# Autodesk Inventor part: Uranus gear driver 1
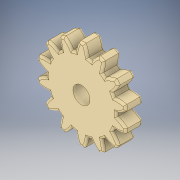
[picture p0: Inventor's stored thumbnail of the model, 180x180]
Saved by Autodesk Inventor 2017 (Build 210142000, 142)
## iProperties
Created: 2016-06
Part Number: Uranus gear driver 1
Material: Generic
Document SubType Name: Modeling
Designer: Stan
Density: 1 g/cm^3
Appearance: Beige
Author: Stan
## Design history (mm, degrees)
sketch "Sketch1"
  geometry: A1 r 11.074 centre (-14.504, 0.302) between (-8.695, 9.73) and (-12.531, 11.198); A2 r 11.074 centre (-14.504, 0.302) between (-8.695, 9.73) and (-12.531, 11.198); A3 r 11.074 centre (2.933, 14.207) between (-8.129, 14.709) and (-7.551, 10.642); A4 r 11.074 centre (2.933, 14.207) between (-8.129, 14.709) and (-7.551, 10.642); A5 r 11.074 centre (-13.198, -6.021) between (-12.056, 4.994) and (-16.149, 4.652); A6 r 11.074 centre (-13.198, -6.021) between (-12.056, 4.994) and (-16.149, 4.652); A7 r 11.074 centre (-3.521, 14.073) between (-13.706, 9.725) and (-11.421, 6.312); A8 r 11.074 centre (-3.521, 14.073) between (-13.706, 9.725) and (-11.421, 6.312); A9 r 11.074 centre (-9.279, -11.152) between (-13.029, -0.732) and (-16.568, -2.815); A10 r 11.074 centre (-9.279, -11.152) between (-13.029, -0.732) and (-16.568, -2.815); A11 r 11.074 centre (-9.279, 11.152) between (-16.568, 2.815) and (-13.029, 0.732); A12 r 11.074 centre (-9.279, 11.152) between (-16.568, 2.815) and (-13.029, 0.732); A13 r 11.074 centre (-3.521, -14.073) between (-11.421, -6.312) and (-13.706, -9.725); A14 r 11.074 centre (-3.521, -14.073) between (-11.421, -6.312) and (-13.706, -9.725); A15 r 11.074 centre (-13.198, 6.021) between (-16.149, -4.652) and (-12.056, -4.994); A16 r 11.074 centre (-13.198, 6.021) between (-16.149, -4.652) and (-12.056, -4.994); A17 r 11.074 centre (2.933, -14.207) between (-7.551, -10.642) and (-8.129, -14.709); A18 r 11.074 centre (2.933, -14.207) between (-7.551, -10.642) and (-8.129, -14.709); A19 r 11.074 centre (-14.504, -0.302) between (-12.531, -11.198) and (-8.695, -9.73); A20 r 11.074 centre (-14.504, -0.302) between (-12.531, -11.198) and (-8.695, -9.73); A21 r 11.074 centre (8.807, -11.528) between (-2.186, -12.865) and (-0.942, -16.779); A22 r 11.074 centre (8.807, -11.528) between (-2.186, -12.865) and (-0.942, -16.779); A23 r 11.074 centre (-12.937, -6.565) between (-6.431, -15.526) and (-3.612, -12.539); A24 r 11.074 centre (-12.937, -6.565) between (-6.431, -15.526) and (-3.612, -12.539); A25 r 11.074 centre (12.937, -6.565) between (3.612, -12.539) and (6.431, -15.526); A26 r 11.074 centre (12.937, -6.565) between (3.612, -12.539) and (6.431, -15.526); A27 r 11.074 centre (-8.807, -11.528) between (0.942, -16.779) and (2.186, -12.865); A28 r 11.074 centre (-8.807, -11.528) between (0.942, -16.779) and (2.186, -12.865); A29 r 11.074 centre (14.504, -0.302) between (8.695, -9.73) and (12.531, -11.198); A30 r 11.074 centre (14.504, -0.302) between (8.695, -9.73) and (12.531, -11.198); A31 r 11.074 centre (-2.933, -14.207) between (8.129, -14.709) and (7.551, -10.642); A32 r 11.074 centre (-2.933, -14.207) between (8.129, -14.709) and (7.551, -10.642); A33 r 11.074 centre (13.198, 6.021) between (12.056, -4.994) and (16.149, -4.652); A34 r 11.074 centre (13.198, 6.021) between (12.056, -4.994) and (16.149, -4.652); A35 r 11.074 centre (3.521, -14.073) between (13.706, -9.725) and (11.421, -6.312); A36 r 11.074 centre (3.521, -14.073) between (13.706, -9.725) and (11.421, -6.312); A37 r 11.074 centre (9.279, 11.152) between (13.029, 0.732) and (16.568, 2.815); A38 r 11.074 centre (9.279, 11.152) between (13.029, 0.732) and (16.568, 2.815); A39 r 11.074 centre (9.279, -11.152) between (16.568, -2.815) and (13.029, -0.732); A40 r 11.074 centre (9.279, -11.152) between (16.568, -2.815) and (13.029, -0.732); A41 r 11.074 centre (3.521, 14.073) between (11.421, 6.312) and (13.706, 9.725); A42 r 11.074 centre (3.521, 14.073) between (11.421, 6.312) and (13.706, 9.725); A43 r 11.074 centre (13.198, -6.021) between (16.149, 4.652) and (12.056, 4.994); A44 r 11.074 centre (13.198, -6.021) between (16.149, 4.652) and (12.056, 4.994); A45 r 11.074 centre (-2.933, 14.207) between (7.551, 10.642) and (8.129, 14.709); A46 r 11.074 centre (-2.933, 14.207) between (7.551, 10.642) and (8.129, 14.709); A47 r 11.074 centre (14.504, 0.302) between (12.531, 11.198) and (8.695, 9.73); A48 r 11.074 centre (14.504, 0.302) between (12.531, 11.198) and (8.695, 9.73); A49 r 11.074 centre (-8.807, 11.528) between (2.186, 12.865) and (0.942, 16.779); A50 r 11.074 centre (-8.807, 11.528) between (2.186, 12.865) and (0.942, 16.779); A51 r 11.074 centre (12.937, 6.565) between (6.431, 15.526) and (3.612, 12.539); A52 r 11.074 centre (12.937, 6.565) between (6.431, 15.526) and (3.612, 12.539); A53 r 11.074 centre (2.933, 14.207) between (-8.129, 14.709) and (-7.551, 10.642); A54 r 11.074 centre (-14.504, 0.302) between (-8.695, 9.73) and (-12.531, 11.198); A55 r 11.074 centre (-3.521, 14.073) between (-13.706, 9.725) and (-11.421, 6.312); A56 r 11.074 centre (-13.198, -6.021) between (-12.056, 4.994) and (-16.149, 4.652); A57 r 11.074 centre (-9.279, 11.152) between (-16.568, 2.815) and (-13.029, 0.732); A58 r 11.074 centre (-9.279, -11.152) between (-13.029, -0.732) and (-16.568, -2.815); A59 r 11.074 centre (-13.198, 6.021) between (-16.149, -4.652) and (-12.056, -4.994); A60 r 11.074 centre (-3.521, -14.073) between (-11.421, -6.312) and (-13.706, -9.725); A61 r 11.074 centre (-14.504, -0.302) between (-12.531, -11.198) and (-8.695, -9.73); A62 r 11.074 centre (2.933, -14.207) between (-7.551, -10.642) and (-8.129, -14.709); A63 r 11.074 centre (-12.937, -6.565) between (-6.431, -15.526) and (-3.612, -12.539); A64 r 11.074 centre (8.807, -11.528) between (-2.186, -12.865) and (-0.942, -16.779)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; 1 further point
  constraints: 224 point on circle, 112 centre point, 8 horizontal alignment, 8 vertical alignment, 320 other
extrude "Extrusion1" new body sketch "Sketch1" distance "d0" = 6.35; taper "d1" = 0 deg
sketch "Sketch2"
  geometry: C1 r 3.175 at (0, 0); 1 further point
  constraints: 1 centre point, 1 coincident
  dimensions: "d2" = 6.35 diameter of C1
extrude "Extrusion2" cut sketch "Sketch2" distance "d3" = 6.35; taper "d4" = 0 deg
fillet "Fillet1" dims "d5" = 0.79375
body "Solid1"
